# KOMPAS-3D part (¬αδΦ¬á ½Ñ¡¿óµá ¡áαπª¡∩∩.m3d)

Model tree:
1. Эскиз:1
2. Операция выдавливания:1
     Расстояние 1 = 1; Расстояние 2 = 1
3. Эскиз:3
4. Операция выдавливания:5
     Расстояние 1 = 1; Расстояние 2 = 1
5. Скругление:3
     Радиус = 0.5
6. Скругление:4
     Радиус = 0.5
7. Массив по концентрической сетке:5  (with: Операция выдавливания:5, Скругление:3, Скругление:4)  (labels: Экземпляр ( 1, 1 ); Экземпляр ( 1, 2 ); Экземпляр ( 1, 3 ); Экземпляр ( 1, 4 ))
     N 2 = 10; Шаг 2 = 360
8. Скругление:6
     Радиус = 0.1
9. Скругление:7
     Радиус = 0.1
10. Эскиз:4
11. Операция выдавливания:6
     Расстояние 1 = 2.5; Угол 1 = 30; Расстояние 2 = 1
12. Скругление:9
     Радиус = 0.1
13. Скругление:10
     Радиус = 2
14. Эскиз:5
15. Операция выдавливания:7
     Расстояние 1 = 0.3; Расстояние 2 = 1
16. Эскиз:6
17. Операция выдавливания:8
     Расстояние 1 = 0.2; Расстояние 2 = 1
18. Скругление:11
     Радиус = 0.1
19. Эскиз:7
20. Операция выдавливания:9
     Расстояние 1 = 0.2; Расстояние 2 = 1
21. Эскиз:8
22. Операция выдавливания:10
     Расстояние 1 = 0.5; Расстояние 2 = 1
23. Массив по концентрической сетке:6  (with: Операция выдавливания:9, Операция выдавливания:10)  (labels: Экземпляр ( 1, 1 ); Экземпляр ( 1, 2 ); Экземпляр ( 1, 3 ); Экземпляр ( 1, 4 ))
     N 2 = 10; Шаг 2 = 360
24. Эскиз:10
25. Отверстие:1
26. Скругление:12
     Радиус = 0.1

Referenced files in C:\Program Files\ASCON\KOMPAS-3D V13 Home\Sys\: holelib.lfr
Referenced files in C:\Program Files\ASCON\KOMPAS-3D V12\Sys\: holelib.lfr
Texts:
  крышка ленивца наружняя
  Сплав АЛ8  ГОСТ 1583-93
  Отверстие 02
  (вариант 2)
  Номер 1
  Номер 2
